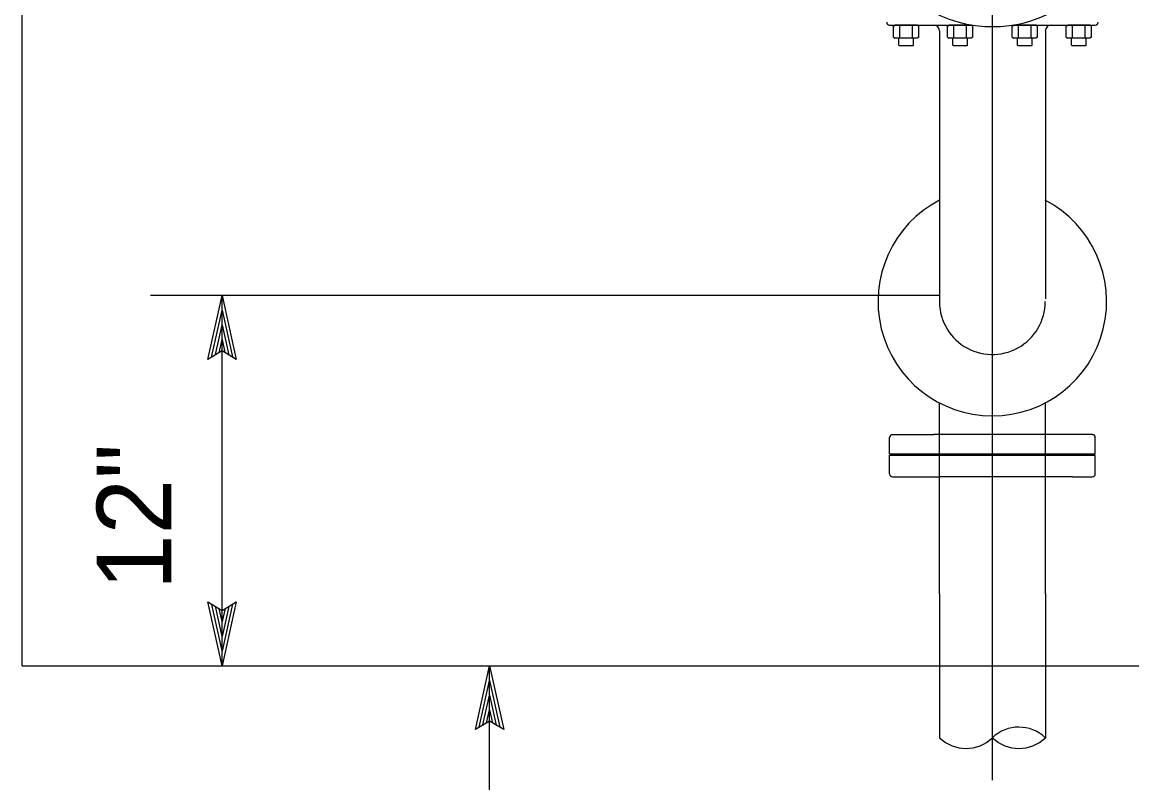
# Model space of a CAD drawing. Extents: x -1680 to 1155, y -802 to 799.
# Drawn here: x 212.1 to 316.4, y -549.1 to -477.7 of the extents above; entities that cross this region are included whole.
import ezdxf

# ---------------------------------------------------------------- set-up
doc = ezdxf.new("R2010")
doc.units = 0
doc.layers.add('Misc CnstDet(22)', color=7, linetype='Continuous')

msp = doc.modelspace()

# ---------------------------------------------------------------- linework, layer by layer
at = {"layer": 'Misc CnstDet(22)'}
for p, q in [((303.25, -548.83), (303.25, -300.88)), ((212.09, -538.09), (212.09, -312.88)), ((293.6, -477.93), (301.44, -477.93)), ((293.95, -478.02), (294.11, -477.93)), ((293.95, -479.07), (293.95, -478.02)), ((296.18, -477.93), (294.11, -477.93)), ((294.55, -479.07), (294.55, -478.03)), ((295.74, -479.07), (295.74, -478.03)), ((296.34, -478.02), (296.18, -477.93)), ((296.34, -479.07), (296.34, -478.02)), ((298.29, -478.48), (298.29, -503.63)), ((299.03, -478.02), (299.19, -477.93)), ((299.03, -479.07), (299.03, -478.02)), ((301.26, -477.93), (299.19, -477.93)), ((299.63, -479.07), (299.63, -478.03)), ((300.82, -479.07), (300.82, -478.03)), ((301.42, -478.02), (301.26, -477.93)), ((301.42, -479.07), (301.42, -478.02)), ((305.09, -477.93), (312.92, -477.93)), ((305.1, -478.02), (305.26, -477.93)), ((305.1, -479.07), (305.1, -478.02)), ((307.33, -477.93), (305.26, -477.93)), ((305.7, -479.07), (305.7, -478.03)), ((306.9, -479.07), (306.9, -478.03)), ((307.49, -478.02), (307.33, -477.93)), ((307.49, -479.07), (307.49, -478.02)), ((308.23, -478.48), (308.23, -503.63)), ((310.18, -478.02), (310.34, -477.93)), ((310.18, -479.07), (310.18, -478.02)), ((312.41, -477.93), (310.34, -477.93)), ((310.78, -479.07), (310.78, -478.03)), ((311.97, -479.07), (311.97, -478.03)), ((312.57, -478.02), (312.41, -477.93)), ((312.57, -479.07), (312.57, -478.02)), ((293.95, -479.07), (294.11, -479.17)), ((296.18, -479.17), (294.11, -479.17)), ((294.46, -479.8), (294.46, -479.17)), ((295.84, -479.8), (295.84, -479.17)), ((296.34, -479.07), (296.18, -479.17)), ((299.03, -479.07), (299.19, -479.17)), ((301.26, -479.17), (299.19, -479.17)), ((299.53, -479.8), (299.53, -479.17)), ((300.91, -479.8), (300.91, -479.17)), ((301.42, -479.07), (301.26, -479.17)), ((305.1, -479.07), (305.26, -479.17)), ((307.33, -479.17), (305.26, -479.17)), ((305.61, -479.8), (305.61, -479.17)), ((306.99, -479.8), (306.99, -479.17)), ((307.49, -479.07), (307.33, -479.17)), ((310.18, -479.07), (310.34, -479.17)), ((312.41, -479.17), (310.34, -479.17)), ((310.69, -479.8), (310.69, -479.17)), ((312.07, -479.8), (312.07, -479.17)), ((312.57, -479.07), (312.41, -479.17)), ((294.52, -479.86), (294.46, -479.8)), ((295.77, -479.86), (294.52, -479.86)), ((295.77, -479.86), (295.84, -479.8)), ((299.6, -479.86), (299.53, -479.8)), ((300.85, -479.86), (299.6, -479.86)), ((300.85, -479.86), (300.91, -479.8)), ((305.67, -479.86), (305.61, -479.8)), ((306.92, -479.86), (305.67, -479.86)), ((306.92, -479.86), (306.99, -479.8)), ((310.75, -479.86), (310.69, -479.8)), ((312, -479.86), (310.75, -479.86)), ((312, -479.86), (312.07, -479.8)), ((298.29, -503.32), (224.16, -503.32)), ((229.53, -509.32), (230.87, -503.32)), ((230.87, -503.32), (230.87, -503.32)), ((230.87, -503.32), (232.2, -509.32)), ((230.87, -538.09), (230.87, -503.32)), ((229.89, -509.1), (230.87, -504.7)), ((230.88, -504.71), (231.84, -509.08)), ((230.25, -508.87), (230.87, -506.08)), ((230.87, -506.08), (231.5, -508.91)), ((230.59, -508.69), (230.87, -507.46)), ((230.87, -507.46), (231.14, -508.67)), ((230.87, -508.52), (229.53, -509.32)), ((232.2, -509.32), (230.87, -508.52)), ((229.53, -509.32), (229.53, -509.32)), ((232.2, -509.32), (232.2, -509.32)), ((298.29, -531.34), (298.29, -513.42)), ((308.23, -531.34), (308.23, -513.41)), ((293.59, -518.2), (293.59, -516.65)), ((293.85, -516.39), (297.76, -516.39)), ((308.76, -516.39), (297.76, -516.39)), ((312.66, -516.39), (308.75, -516.39)), ((312.91, -518.2), (312.91, -516.65)), ((293.59, -518.2), (307.64, -518.2)), ((307.64, -518.2), (312.91, -518.2)), ((293.59, -520.07), (293.59, -518.33)), ((293.59, -518.33), (307.93, -518.33)), ((307.93, -518.33), (312.92, -518.33)), ((312.92, -520.07), (312.92, -518.33)), ((293.87, -520.35), (298.27, -520.35)), ((310.79, -520.35), (298.27, -520.35)), ((310.79, -520.35), (312.64, -520.35)), ((298.29, -531.34), (298.29, -544.86)), ((308.23, -531.34), (308.23, -544.86)), ((230.87, -538.09), (229.54, -532.09)), ((229.54, -532.09), (229.54, -532.09)), ((229.54, -532.09), (230.87, -532.89)), ((230.87, -536.7), (229.9, -532.33)), ((230.87, -535.33), (230.25, -532.5)), ((230.88, -533.95), (230.61, -532.74)), ((230.87, -532.89), (232.21, -532.09)), ((232.21, -532.09), (230.87, -538.09)), ((231.86, -532.31), (230.87, -536.71)), ((231.5, -532.54), (230.87, -535.33)), ((231.15, -532.72), (230.88, -533.95)), ((232.21, -532.09), (232.21, -532.09)), ((212.09, -538.09), (565.93, -538.09)), ((230.87, -538.09), (230.87, -538.09)), ((254.67, -544.09), (256.01, -538.09)), ((256.01, -538.09), (256.01, -538.09)), ((256.01, -538.09), (257.34, -544.09)), ((256.01, -590.18), (256.01, -538.09)), ((255.02, -543.87), (256.01, -539.47)), ((256.01, -539.48), (256.98, -543.86)), ((255.38, -543.64), (256.01, -540.85)), ((256.01, -540.85), (256.63, -543.68)), ((255.73, -543.46), (256.01, -542.23)), ((256.01, -542.23), (256.27, -543.44)), ((256.01, -543.29), (254.67, -544.09)), ((254.67, -544.09), (254.67, -544.09)), ((257.34, -544.09), (256.01, -543.29)), ((257.34, -544.09), (257.34, -544.09))]:
    msp.add_line(p, q, dxfattribs=at)
for centre, radius, start, end in [((303.26, -465.93), 12.14, 76.8634, 270.7347), ((303.26, -465.93), 12.14, 270.9106, 76.8634), ((293.6, -477.66), 0.276, 180, 270), ((297.74, -478.48), 0.552, 0, 90), ((308.78, -478.48), 0.552, 90, 180), ((312.92, -477.66), 0.276, 270, 0), ((312.92, -477.66), 0.276, 270, 320.9284), ((303.25, -503.89), 10.74, 117.5041, 62.4289), ((303.25, -503.89), 4.97, 176.9128, 359.9994), ((293.85, -516.65), 0.258, 90, 180), ((312.66, -516.65), 0.258, 0, 90), ((293.87, -520.07), 0.279, 180, 270), ((312.64, -520.07), 0.279, 270, 0), ((305.74, -547.46), 3.6, 46.3237, 133.5967), ((300.78, -542.24), 3.61, 226.5226, 313.5571), ((305.75, -542.24), 3.61, 226.461, 313.4594)]:
    msp.add_arc(centre, radius, start, end, dxfattribs=at)

# ---------------------------------------------------------------- texts
msp.add_text('12"', height=7, rotation=90, dxfattribs=at).set_placement((226.09, -530.97))

doc.saveas('drawing.dxf')
